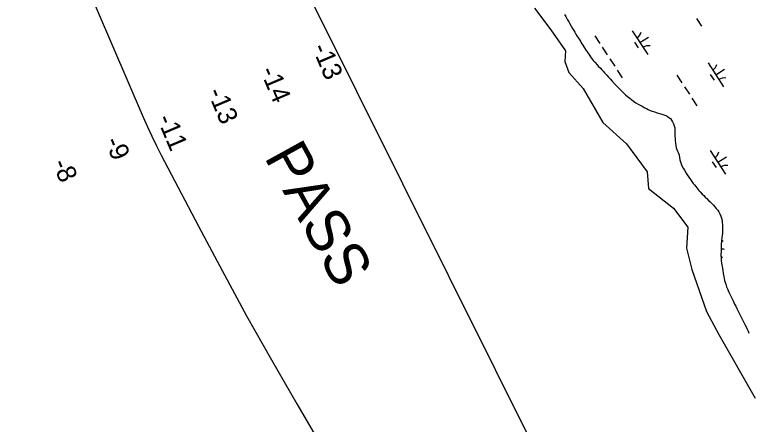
# Model space of a CAD drawing. Extents: x 3953924 to 3974542, y 193747 to 216192.
# Drawn here: x 3960826 to 3962117, y 208038 to 208758 of the extents above; entities that cross this region are included whole.
import ezdxf

# ---------------------------------------------------------------- set-up
doc = ezdxf.new("R2010")
doc.units = 0
for name, color, linetype in [('V-RIVR-EDGE', 7, 'Continuous'), ('V-RIVR-IDEN', 7, 'Continuous'), ('V-RIVR-RANG', 7, 'Continuous'), ('V-TOPO-DPTH', 7, 'Continuous'), ('V-TOPO-MINR', 7, 'Continuous'), ('V-WETL-SWMP', 7, 'Continuous')]:
    doc.layers.add(name, color=color, linetype=linetype)

msp = doc.modelspace()

# ---------------------------------------------------------------- linework, layer by layer
at = {"layer": 'V-RIVR-EDGE'}
msp.add_lwpolyline([(3961741, 208769.1), (3961769.5, 208731.2), (3961795.6, 208694.3), (3961794.4, 208675.4), (3961801.6, 208656.4), (3961826.5, 208627.9), (3961860.9, 208568.5), (3961902.5, 208530.5), (3961939.3, 208481.8), (3961941.7, 208452.2), (3961985.6, 208417.7), (3962010.5, 208384.5), (3962008.1, 208347.7), (3962017.6, 208309.7), (3962043.8, 208236.1), (3962065.1, 208195.7), (3962129.2, 208084.1)], dxfattribs=at)
at = {"layer": 'V-TOPO-DPTH'}
for points in [[(3961753.3, 207971.3), (3960371.5, 210740.9)], [(3960838.1, 209075.7), (3961052.4, 208577.9), (3961059.9, 208560.9), (3961067.7, 208544.1), (3961075.9, 208527.4), (3961084.3, 208510.9), (3961149.8, 208385.8), (3961191.7, 208307.1), (3961234.3, 208228.8), (3961278, 208151.1), (3961322.5, 208073.9), (3961525.5, 207726.8)]]:
    msp.add_lwpolyline(points, dxfattribs=at)
at = {"layer": 'V-TOPO-MINR'}
msp.add_lwpolyline([(3960838.1, 209075.7), (3961052.4, 208577.9), (3961059.9, 208560.9), (3961067.7, 208544.1), (3961075.9, 208527.4), (3961084.3, 208510.9), (3961149.8, 208385.8), (3961191.7, 208307.1), (3961234.3, 208228.8), (3961278, 208151.1), (3961322.5, 208073.9), (3961525.5, 207726.8)], dxfattribs=at)
at = {"layer": 'V-WETL-SWMP'}
for p, q in [((3961793.8, 208758), (3961795.8, 208754.7)), ((3961795.8, 208754.7), (3961799.2, 208748.7)), ((3961799.2, 208748.7), (3961801.2, 208745.3)), ((3961801.2, 208745.3), (3961802.7, 208742.6)), ((3962025.8, 208751), (3962034.5, 208737.6)), ((3961802.7, 208742.6), (3961805.7, 208737.5)), ((3961805.7, 208737.5), (3961807.9, 208733.6)), ((3961807.9, 208733.6), (3961810.2, 208729.9)), ((3961810.2, 208729.9), (3961811.6, 208727.2)), ((3961811.6, 208727.2), (3961813.3, 208724.4)), ((3961813.3, 208724.4), (3961815.5, 208720.7)), ((3961815.5, 208720.7), (3961819.3, 208714.7)), ((3961847.1, 208720.6), (3961855.8, 208707.2)), ((3961912.9, 208729.6), (3961940.2, 208687.7)), ((3961819.3, 208714.7), (3961821.8, 208710.9)), ((3961821.8, 208710.9), (3961823.3, 208708.2)), ((3961823.3, 208708.2), (3961826.1, 208704.2)), ((3961916.8, 208709.4), (3961923.4, 208699.4)), ((3961926.5, 208708.6), (3961941.6, 208718.4)), ((3961826.1, 208704.2), (3961827.7, 208701.1)), ((3961827.7, 208701.1), (3961830.6, 208696.6)), ((3961830.6, 208696.6), (3961834.7, 208690.5)), ((3961860.2, 208700.5), (3961868.9, 208687.1)), ((3961834.7, 208690.5), (3961837.6, 208686.3)), ((3961837.6, 208686.3), (3961839.5, 208683.8)), ((3961839.5, 208683.8), (3961842.5, 208679.8)), ((3961842.5, 208679.8), (3961844.4, 208677.4)), ((3961844.4, 208677.4), (3961847.1, 208674.2)), ((3961847.1, 208674.2), (3961851.2, 208669.5)), ((3961851.2, 208669.5), (3961853.6, 208666.8)), ((3961873.3, 208680.4), (3961882, 208667)), ((3962046.3, 208673), (3962073.6, 208631.1)), ((3961853.6, 208666.8), (3961856.9, 208663.5)), ((3961856.9, 208663.5), (3961859.5, 208661.1)), ((3961859.5, 208661.1), (3961861.9, 208658.3)), ((3961861.9, 208658.3), (3961864.3, 208655.7)), ((3961864.3, 208655.7), (3961868.2, 208651.5)), ((3961886.4, 208660.3), (3961895.1, 208646.9)), ((3962060, 208652), (3962075.1, 208661.8)), ((3961868.2, 208651.5), (3961871.1, 208648.2)), ((3961871.1, 208648.2), (3961873.9, 208645)), ((3961873.9, 208645), (3961877.8, 208640.7)), ((3961991.6, 208651.3), (3962000.3, 208637.9)), ((3962050.2, 208652.8), (3962056.8, 208642.8)), ((3961877.8, 208640.7), (3961882.6, 208635.2)), ((3961882.6, 208635.2), (3961887.7, 208630.2)), ((3961887.7, 208630.2), (3961892.2, 208625.7)), ((3962004.7, 208631.2), (3962013.4, 208617.8)), ((3961892.2, 208625.7), (3961894.9, 208622.8)), ((3961894.9, 208622.8), (3961898.9, 208619.1)), ((3961898.9, 208619.1), (3961901.2, 208617.1)), ((3961901.2, 208617.1), (3961904.7, 208614)), ((3961904.7, 208614), (3961908.5, 208611)), ((3961908.5, 208611), (3961911.4, 208608.6)), ((3961911.4, 208608.6), (3961915.3, 208605.7)), ((3961915.3, 208605.7), (3961919.2, 208603.1)), ((3962017.8, 208611), (3962026.5, 208597.6)), ((3961919.2, 208603.1), (3961923.2, 208600.6)), ((3961923.2, 208600.6), (3961925.8, 208599.1)), ((3961925.8, 208599.1), (3961930.3, 208596.7)), ((3961930.3, 208596.7), (3961935.1, 208594.1)), ((3961935.1, 208594.1), (3961938, 208592.6)), ((3961938, 208592.6), (3961940.9, 208590.9)), ((3961940.9, 208590.9), (3961944.3, 208589.5)), ((3961944.3, 208589.5), (3961948, 208587.9)), ((3961948, 208587.9), (3961952.3, 208586.8)), ((3961952.3, 208586.8), (3961956.7, 208585.5)), ((3961956.7, 208585.5), (3961960.8, 208584.3)), ((3961960.8, 208584.3), (3961965, 208583)), ((3961965, 208583), (3961968.5, 208581.9)), ((3961968.5, 208581.9), (3961971.7, 208580.8)), ((3961971.7, 208580.8), (3961974.5, 208579.4)), ((3961974.5, 208579.4), (3961977.5, 208577.3)), ((3961977.5, 208577.3), (3961980, 208575)), ((3961980, 208575), (3961982.2, 208572.4)), ((3961982.2, 208572.4), (3961983.9, 208569.5)), ((3961983.9, 208569.5), (3961985.3, 208566)), ((3961985.3, 208566), (3961986.7, 208562.2)), ((3961986.7, 208562.2), (3961987.6, 208559.1)), ((3961987.6, 208559.1), (3961987.9, 208555.8)), ((3961987.9, 208555.8), (3961988.1, 208550.5)), ((3961988.1, 208550.5), (3961988, 208544.8)), ((3961988, 208544.8), (3961988.2, 208539.6)), ((3961988.2, 208539.6), (3961988.5, 208536.5)), ((3961988.5, 208536.5), (3961988.9, 208531.8)), ((3961988.9, 208531.8), (3961989.7, 208527.7)), ((3961989.7, 208527.7), (3961990.4, 208524)), ((3961990.4, 208524), (3961991.4, 208520.7)), ((3961991.4, 208520.7), (3961992.5, 208517.7)), ((3961992.5, 208517.7), (3961994.4, 208514.2)), ((3961994.4, 208514.2), (3961995.2, 208510.9)), ((3962049.8, 208519.3), (3962077.1, 208477.3)), ((3961995.2, 208510.9), (3961995.9, 208506.7)), ((3961995.9, 208506.7), (3961996.8, 208502.8)), ((3961996.8, 208502.8), (3961997.8, 208499.1)), ((3962063.5, 208498.3), (3962078.5, 208508.1)), ((3961997.8, 208499.1), (3961999, 208495.5)), ((3961999, 208495.5), (3962000.4, 208491.9)), ((3962000.4, 208491.9), (3962002.4, 208487.9)), ((3962002.4, 208487.9), (3962004.6, 208484.4)), ((3962053.7, 208499.1), (3962060.3, 208489.1)), ((3962004.6, 208484.4), (3962007.7, 208479.3)), ((3962007.7, 208479.3), (3962009.7, 208476.5)), ((3962009.7, 208476.5), (3962012.6, 208472.1)), ((3962012.6, 208472.1), (3962015.3, 208468.1)), ((3962015.3, 208468.1), (3962018, 208464.5)), ((3962018, 208464.5), (3962020.2, 208461.3)), ((3962020.2, 208461.3), (3962022.4, 208458.5)), ((3962022.4, 208458.5), (3962024.7, 208455.8)), ((3962024.7, 208455.8), (3962026.6, 208453.3)), ((3962026.6, 208453.3), (3962030.3, 208448.8)), ((3962030.3, 208448.8), (3962032.5, 208446.3)), ((3962032.5, 208446.3), (3962036.2, 208442.6)), ((3962036.2, 208442.6), (3962038.6, 208440)), ((3962038.6, 208440), (3962041.2, 208437.2)), ((3962041.2, 208437.2), (3962043.9, 208434.5)), ((3962043.9, 208434.5), (3962047.1, 208431.2)), ((3962047.1, 208431.2), (3962049.3, 208429.2)), ((3962049.3, 208429.2), (3962055.6, 208422.8)), ((3962055.6, 208422.8), (3962058.2, 208420)), ((3962058.2, 208420), (3962060.8, 208417.2)), ((3962060.8, 208417.2), (3962063.2, 208414.3)), ((3962063.2, 208414.3), (3962065.1, 208411.3)), ((3962065.1, 208411.3), (3962066.9, 208407.8)), ((3962066.9, 208407.8), (3962068.5, 208403.8)), ((3962068.5, 208403.8), (3962069.9, 208399.9)), ((3962069.9, 208399.9), (3962070.9, 208395.8)), ((3962070.9, 208395.8), (3962071.4, 208392.6)), ((3962071.4, 208392.6), (3962071.8, 208389)), ((3962071.8, 208389), (3962071.9, 208384.5)), ((3962071.9, 208384.5), (3962071.8, 208381.2)), ((3962071.5, 208374), (3962071.1, 208369.8)), ((3962071.7, 208377), (3962071.5, 208374)), ((3962071.8, 208381.2), (3962071.7, 208377)), ((3962070, 208360.2), (3962069.6, 208353.7)), ((3962070.6, 208366), (3962070, 208360.2)), ((3962070, 208359.1), (3962072.6, 208360.8)), ((3962071.1, 208369.8), (3962070.6, 208366)), ((3962069.3, 208346.5), (3962069.1, 208342.3)), ((3962069.6, 208353.7), (3962069.3, 208346.5)), ((3962069.1, 208342.3), (3962069, 208335.7)), ((3962069, 208335.7), (3962069.3, 208329.3)), ((3962069.1, 208333), (3962071.1, 208330)), ((3962069.3, 208329.3), (3962069.5, 208325.7)), ((3962069.5, 208325.7), (3962070.1, 208321)), ((3962070.1, 208321), (3962071, 208315)), ((3962071, 208315), (3962072.1, 208308.8)), ((3962072.1, 208308.8), (3962073.1, 208302.9)), ((3962073.1, 208302.9), (3962074, 208297.6)), ((3962074, 208297.6), (3962074.7, 208294.4)), ((3962074.7, 208294.4), (3962075.4, 208290.7)), ((3962075.4, 208290.7), (3962077.5, 208284)), ((3962077.5, 208284), (3962079, 208279.5)), ((3962079, 208279.5), (3962080.4, 208275.9)), ((3962080.4, 208275.9), (3962082.9, 208270.3)), ((3962082.9, 208270.3), (3962088.2, 208259.6)), ((3962088.2, 208259.6), (3962090.3, 208254.7)), ((3962090.3, 208254.7), (3962091.7, 208251.8)), ((3962091.7, 208251.8), (3962093.1, 208249.1)), ((3962093.1, 208249.1), (3962095.1, 208245.6)), ((3962095.1, 208245.6), (3962096.9, 208241.5)), ((3962096.9, 208241.5), (3962101.4, 208232.3)), ((3962101.4, 208232.3), (3962104, 208227.1)), ((3962104, 208227.1), (3962108.2, 208219.1)), ((3962108.2, 208219.1), (3962111.1, 208213.1)), ((3962111.1, 208213.1), (3962113.2, 208208.9)), ((3962113.2, 208208.9), (3962114.6, 208206)), ((3962114.6, 208206), (3962116.8, 208201.3)), ((3962116.8, 208201.3), (3962118.3, 208198.2))]:
    msp.add_line(p, q, dxfattribs=at)
for centre, start, end in [((3961911.7, 208731.9), 302.2901, 343.8338), ((3961941.8, 208685.6), 82.2901, 123.8337), ((3962045.1, 208675.3), 302.2901, 343.8338), ((3962075.2, 208629), 82.2901, 123.8337), ((3962048.6, 208521.6), 302.2901, 343.8338), ((3962078.7, 208475.3), 82.2901, 123.8337), ((3962072.7, 208327.9), 82.2901, 101.3867)]:
    msp.add_arc(centre, 17.6, start, end, dxfattribs=at)

# ---------------------------------------------------------------- texts
at = {"layer": 'V-RIVR-IDEN'}
msp.add_text('PASS', height=75, rotation=298.8483, dxfattribs=at).set_placement((3961264.4, 208507.8))
at = {"layer": 'V-RIVR-RANG'}
for s, p in [('-13', (3961348.9, 208699.8)), ('-14', (3961257.5, 208659.3)), ('-13', (3961164.8, 208621.9)), ('-11', (3961076, 208575.1)), ('-9', (3960984.2, 208535.4)), ('-8', (3960891.8, 208496.7))]:
    msp.add_text(s, height=33.5, rotation=292.9332, dxfattribs=at).set_placement(p)

doc.saveas('drawing.dxf')
